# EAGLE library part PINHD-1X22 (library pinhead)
PIN HEADER
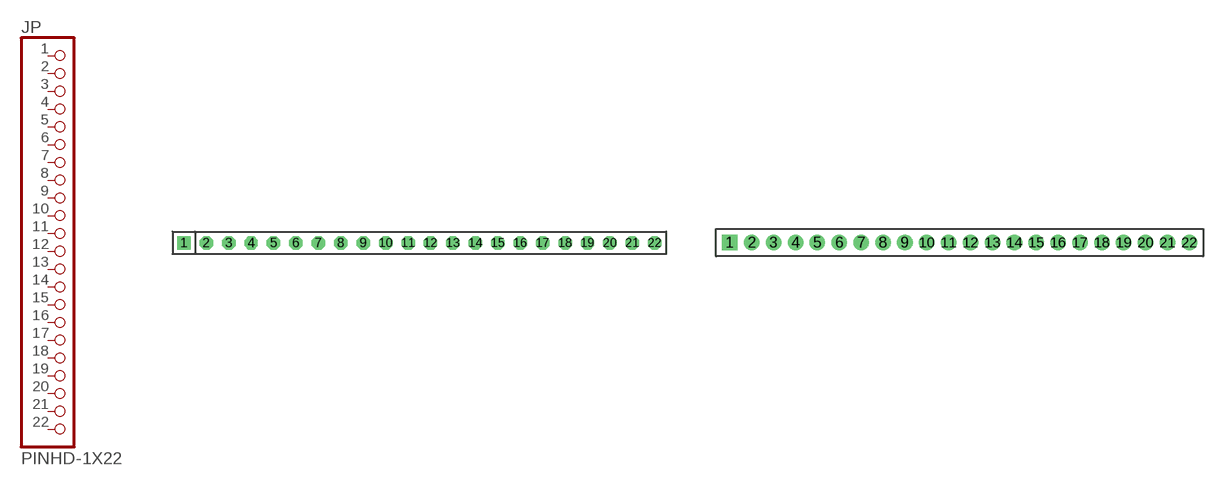
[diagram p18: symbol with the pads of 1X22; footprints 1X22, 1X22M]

Designator prefix JP

## PINHD-1X22  [1X22]
1  1  pas
2  2  pas
3  3  pas
4  4  pas
5  5  pas
6  6  pas
7  7  pas
8  8  pas
9  9  pas
10  10  pas
11  11  pas
12  12  pas
13  13  pas
14  14  pas
15  15  pas
16  16  pas
17  17  pas
18  18  pas
19  19  pas
20  20  pas
21  21  pas
22  22  pas

## PINHD-1X22M  [1X22M]
Pads as for 1X22

## Footprint 1X22 (pad centres in mm)
PIN HEADER - 0.1"
drill 1.016 square: 1 -26.67,0
drill 1.016 octagon: 2 -24.13,0; 3 -21.59,0; 4 -19.05,0; 5 -16.51,0; 6 -13.97,0; 7 -11.43,0; 8 -8.89,0; 9 -6.35,0; 10 -3.81,0; 11 -1.27,0; 12 1.27,0; 13 3.81,0; 14 6.35,0; 15 8.89,0; 16 11.43,0; 17 13.97,0; 18 16.51,0; 19 19.05,0; 20 21.59,0; 21 24.13,0; 22 26.67,0

## Footprint 1X22M (pad centres in mm)
PIN HEADER - 2MM"
drill 0.914 square: 1 -21,0
drill 0.914 round: 2 -19,0; 3 -17,0; 4 -15,0; 5 -13,0; 6 -11,0; 7 -9,0; 8 -7,0; 9 -5,0; 10 -3,0; 11 -1,0; 12 1,0; 13 3,0; 14 5,0; 15 7,0; 16 9,0; 17 11,0; 18 13,0; 19 15,0; 20 17,0; 21 19,0; 22 21,0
